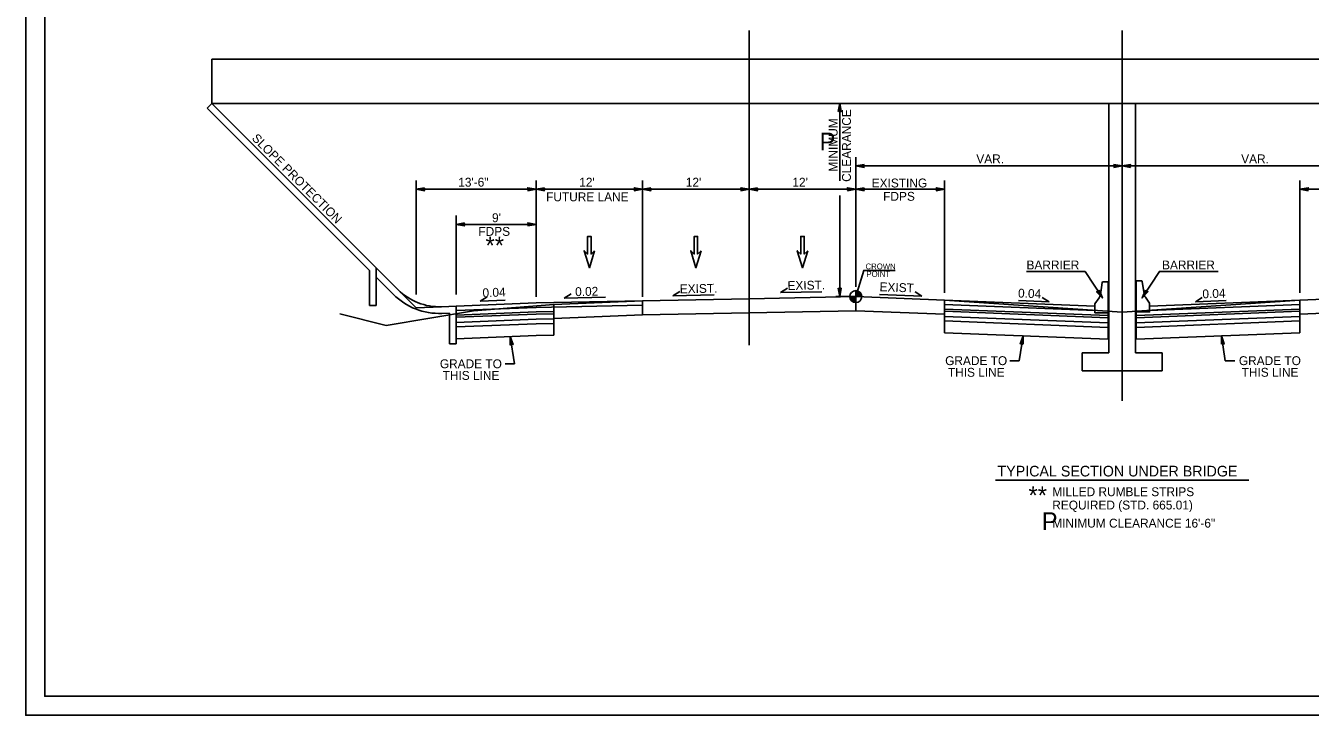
# Model space of a CAD drawing. Extents: x 1553195 to 1553792, y 810516 to 810787.
# Drawn here: x 1553422.4 to 1553567, y 810629 to 810706.7 of the extents above; entities that cross this region are included whole.
import ezdxf

# ---------------------------------------------------------------- set-up
doc = ezdxf.new("R2010")
doc.units = 0
for name, color, linetype in [('Old_Level_11', 7, 'Continuous'), ('Prop Dimension', 7, 'Continuous'), ('Prop DSN Text', 7, 'Continuous'), ('Prop Pavement Schedule Description CELL', 7, 'Continuous'), ('Prop Terminator CELL', 7, 'Continuous'), ('Prop Typical Section', 7, 'Continuous'), ('Sheet Plan CELL', 7, 'Continuous'), ('Typical Arrow Superelevation CELL', 7, 'Continuous'), ('Typical Grade Point Symbol CELL', 7, 'Continuous'), ('Typical Pavement Slope CELL', 7, 'Continuous'), ('Typical Shoulder Slope CELL', 7, 'Continuous'), ('Typical Text ID Circle CELL', 7, 'Continuous'), ('z - Construction', 7, 'Continuous')]:
    doc.layers.add(name, color=color, linetype=linetype)

msp = doc.modelspace()

# ---------------------------------------------------------------- linework, layer by layer
at = {"layer": 'Old_Level_11'}
for p, q in [((1553515.16, 810676.15), (1553515.83, 810676.15)), ((1553515.83, 810676.15), (1553515.83, 810676.82)), ((1553516.5, 810676.15), (1553515.83, 810676.15)), ((1553515.83, 810675.47), (1553515.83, 810676.15)), ((1553515.83, 810676.15), (1553515.83, 810675.47))]:
    msp.add_line(p, q, dxfattribs=at)
for points in [[(1553515.16, 810676.15), (1553515.16, 810676.07)], [(1553515.18, 810676.15), (1553515.18, 810675.99)], [(1553515.19, 810676.15), (1553515.19, 810675.95)], [(1553515.2, 810676.15), (1553515.2, 810675.91)], [(1553515.22, 810676.15), (1553515.22, 810675.87)], [(1553515.23, 810676.15), (1553515.23, 810675.85)], [(1553515.24, 810676.15), (1553515.24, 810675.82)], [(1553515.26, 810676.15), (1553515.26, 810675.8)], [(1553515.27, 810676.15), (1553515.27, 810675.78)], [(1553515.28, 810676.15), (1553515.28, 810675.76)], [(1553515.3, 810676.15), (1553515.3, 810675.74)], [(1553515.31, 810676.15), (1553515.31, 810675.72)], [(1553515.32, 810676.15), (1553515.32, 810675.71)], [(1553515.34, 810676.15), (1553515.34, 810675.69)], [(1553515.35, 810676.15), (1553515.35, 810675.68)], [(1553515.36, 810676.15), (1553515.36, 810675.66)], [(1553515.38, 810676.15), (1553515.38, 810675.65)], [(1553515.39, 810676.15), (1553515.39, 810675.64)], [(1553515.4, 810676.15), (1553515.4, 810675.63)], [(1553515.42, 810676.15), (1553515.42, 810675.62)], [(1553515.43, 810676.15), (1553515.43, 810675.61)], [(1553515.45, 810676.15), (1553515.45, 810675.6)], [(1553515.46, 810676.15), (1553515.46, 810675.59)], [(1553515.47, 810676.15), (1553515.47, 810675.58)], [(1553515.49, 810676.15), (1553515.49, 810675.57)], [(1553515.5, 810676.15), (1553515.5, 810675.56)], [(1553515.51, 810676.15), (1553515.51, 810675.55)], [(1553515.53, 810676.15), (1553515.53, 810675.55)], [(1553515.54, 810676.15), (1553515.54, 810675.54)], [(1553515.55, 810676.15), (1553515.55, 810675.54)], [(1553515.57, 810676.15), (1553515.57, 810675.53)], [(1553515.58, 810676.15), (1553515.58, 810675.52)], [(1553515.59, 810676.15), (1553515.59, 810675.52)], [(1553515.61, 810676.15), (1553515.61, 810675.51)], [(1553515.62, 810676.15), (1553515.62, 810675.51)], [(1553515.63, 810676.15), (1553515.63, 810675.5)], [(1553515.65, 810676.15), (1553515.65, 810675.5)], [(1553515.66, 810676.15), (1553515.66, 810675.5)], [(1553515.67, 810676.15), (1553515.67, 810675.49)], [(1553515.69, 810676.15), (1553515.69, 810675.49)], [(1553515.7, 810676.15), (1553515.7, 810675.49)], [(1553515.71, 810676.15), (1553515.71, 810675.48)], [(1553515.73, 810676.15), (1553515.73, 810675.48)], [(1553515.74, 810676.15), (1553515.74, 810675.48)], [(1553515.75, 810676.15), (1553515.75, 810675.48)], [(1553515.77, 810676.15), (1553515.77, 810675.48)], [(1553515.78, 810676.15), (1553515.78, 810675.48)], [(1553515.79, 810676.15), (1553515.79, 810675.48)], [(1553515.81, 810676.15), (1553515.81, 810675.47)], [(1553515.82, 810676.15), (1553515.82, 810675.47), (1553515.82, 810675.47)], [(1553515.84, 810676.82), (1553515.84, 810676.82), (1553515.84, 810676.15)], [(1553515.85, 810676.82), (1553515.85, 810676.15)], [(1553515.86, 810676.82), (1553515.86, 810676.15)], [(1553515.88, 810676.82), (1553515.88, 810676.15)], [(1553515.89, 810676.81), (1553515.89, 810676.15)], [(1553515.9, 810676.81), (1553515.9, 810676.15)], [(1553515.92, 810676.81), (1553515.92, 810676.15)], [(1553515.93, 810676.81), (1553515.93, 810676.15)], [(1553515.94, 810676.81), (1553515.94, 810676.15)], [(1553515.96, 810676.81), (1553515.96, 810676.15)], [(1553515.97, 810676.8), (1553515.97, 810676.15)], [(1553515.99, 810676.8), (1553515.99, 810676.15)], [(1553516, 810676.8), (1553516, 810676.15)], [(1553516.01, 810676.79), (1553516.01, 810676.15)], [(1553516.03, 810676.79), (1553516.03, 810676.15)], [(1553516.04, 810676.78), (1553516.04, 810676.15)], [(1553516.05, 810676.78), (1553516.05, 810676.15)], [(1553516.07, 810676.78), (1553516.07, 810676.15)], [(1553516.08, 810676.77), (1553516.08, 810676.15)], [(1553516.09, 810676.76), (1553516.09, 810676.15)], [(1553516.11, 810676.76), (1553516.11, 810676.15)], [(1553516.12, 810676.75), (1553516.12, 810676.15)], [(1553516.13, 810676.75), (1553516.13, 810676.15)], [(1553516.15, 810676.74), (1553516.15, 810676.15)], [(1553516.16, 810676.73), (1553516.16, 810676.15)], [(1553516.17, 810676.72), (1553516.17, 810676.15)], [(1553516.19, 810676.72), (1553516.19, 810676.15)], [(1553516.2, 810676.71), (1553516.2, 810676.15)], [(1553516.21, 810676.7), (1553516.21, 810676.15)], [(1553516.23, 810676.69), (1553516.23, 810676.15)], [(1553516.24, 810676.68), (1553516.24, 810676.15)], [(1553516.25, 810676.67), (1553516.25, 810676.15)], [(1553516.27, 810676.66), (1553516.27, 810676.15)], [(1553516.28, 810676.64), (1553516.28, 810676.15)], [(1553516.29, 810676.63), (1553516.29, 810676.15)], [(1553516.31, 810676.62), (1553516.31, 810676.15)], [(1553516.32, 810676.61), (1553516.32, 810676.15)], [(1553516.33, 810676.59), (1553516.33, 810676.15)], [(1553516.35, 810676.57), (1553516.35, 810676.15)], [(1553516.36, 810676.56), (1553516.36, 810676.15)], [(1553516.37, 810676.54), (1553516.37, 810676.15)], [(1553516.39, 810676.52), (1553516.39, 810676.15)], [(1553516.4, 810676.5), (1553516.4, 810676.15)], [(1553516.41, 810676.48), (1553516.41, 810676.15)], [(1553516.43, 810676.45), (1553516.43, 810676.15)], [(1553516.44, 810676.42), (1553516.44, 810676.15)], [(1553516.46, 810676.39), (1553516.46, 810676.15)], [(1553516.47, 810676.36), (1553516.47, 810676.15)], [(1553516.48, 810676.31), (1553516.48, 810676.15)], [(1553516.5, 810676.24), (1553516.5, 810676.15)]]:
    msp.add_lwpolyline(points, dxfattribs=at)
msp.add_circle((1553515.83, 810676.15), 0.671, dxfattribs=at)
for start, end in [(179.9905, 269.9905), (359.9905, 89.9905)]:
    msp.add_arc((1553515.83, 810676.15), 0.671, start, end, dxfattribs=at)
at = {"layer": 'Prop Dimension'}
for p, q in [((1553473.55, 810675.64), (1553474.32, 810676.13)), ((1553483, 810675.98), (1553483.78, 810676.45)), ((1553483, 810675.98), (1553487.66, 810676.07)), ((1553495.23, 810676.25), (1553496.02, 810676.72)), ((1553495.23, 810676.25), (1553499.89, 810676.34)), ((1553507.36, 810676.61), (1553508.15, 810677.08)), ((1553507.36, 810676.61), (1553512.02, 810676.7)), ((1553523.27, 810676.21), (1553518.49, 810676.4)), ((1553523.27, 810676.21), (1553522.5, 810676.7)), ((1553473.55, 810675.64), (1553476.34, 810675.76)), ((1553537.6, 810675.57), (1553534.15, 810675.71)), ((1553537.6, 810675.57), (1553536.82, 810676.06)), ((1553554.07, 810675.57), (1553554.84, 810676.06)), ((1553554.07, 810675.57), (1553557.52, 810675.71))]:
    msp.add_line(p, q, dxfattribs=at)
at = {"layer": 'Prop DSN Text'}
for points in [[(1553513.86, 810696.99), (1553514.02, 810697.93), (1553514.19, 810696.99), (1553514.02, 810697.11)], [(1553516.77, 810691.02), (1553515.83, 810690.86), (1553516.77, 810690.69), (1553516.65, 810690.86)], [(1553544.89, 810690.7), (1553545.83, 810690.86), (1553544.89, 810691.02), (1553545.01, 810690.86)], [(1553546.77, 810690.7), (1553545.83, 810690.86), (1553546.77, 810691.02), (1553546.65, 810690.86)], [(1553467.27, 810688.39), (1553466.33, 810688.23), (1553467.27, 810688.07), (1553467.15, 810688.23)], [(1553478.89, 810688.07), (1553479.83, 810688.23), (1553478.89, 810688.4), (1553479.01, 810688.23)], [(1553480.77, 810688.39), (1553479.83, 810688.23), (1553480.77, 810688.07), (1553480.65, 810688.23)], [(1553490.89, 810688.07), (1553491.83, 810688.23), (1553490.89, 810688.4), (1553491.01, 810688.23)], [(1553492.77, 810688.39), (1553491.83, 810688.23), (1553492.77, 810688.07), (1553492.65, 810688.23)], [(1553502.89, 810688.07), (1553503.83, 810688.23), (1553502.89, 810688.4), (1553503.01, 810688.23)], [(1553504.77, 810688.39), (1553503.83, 810688.23), (1553504.77, 810688.07), (1553504.65, 810688.23)], [(1553514.89, 810688.07), (1553515.83, 810688.23), (1553514.89, 810688.4), (1553515.01, 810688.23)], [(1553516.77, 810688.39), (1553515.83, 810688.23), (1553516.77, 810688.07), (1553516.65, 810688.23)], [(1553524.89, 810688.07), (1553525.83, 810688.23), (1553524.89, 810688.4), (1553525.01, 810688.23)], [(1553566.77, 810688.07), (1553565.83, 810688.23), (1553566.77, 810688.4), (1553566.65, 810688.23)], [(1553471.77, 810684.44), (1553470.83, 810684.28), (1553471.77, 810684.11), (1553471.65, 810684.28)], [(1553478.89, 810684.12), (1553479.83, 810684.28), (1553478.89, 810684.45), (1553479.01, 810684.28)], [(1553513.86, 810677.08), (1553514.02, 810676.15), (1553514.19, 810677.09), (1553514.02, 810676.97)], [(1553543.22, 810676.87), (1553543.6, 810676), (1553542.94, 810676.69), (1553543.15, 810676.68)], [(1553548.44, 810676.87), (1553548.06, 810676), (1553548.72, 810676.69), (1553548.51, 810676.68)], [(1553534.68, 810670.78), (1553534.66, 810671.73), (1553534.35, 810670.82), (1553534.53, 810670.91)], [(1553556.99, 810670.78), (1553557, 810671.73), (1553557.31, 810670.82), (1553557.13, 810670.91)], [(1553476.91, 810670.69), (1553476.93, 810671.64), (1553477.24, 810670.74), (1553477.06, 810670.83)]]:
    msp.add_lwpolyline(points, close=True, dxfattribs=at)
at = {"layer": 'Prop Pavement Schedule Description CELL'}
for p, q in [((1553466.33, 810676.37), (1553466.33, 810689.23)), ((1553470.83, 810676.38), (1553470.83, 810685.28)), ((1553534.23, 810668.92), (1553534.66, 810671.73)), ((1553557.43, 810668.92), (1553557, 810671.73)), ((1553477.4, 810668.56), (1553476.93, 810671.64)), ((1553534.23, 810668.92), (1553533.17, 810668.92)), ((1553557.43, 810668.92), (1553558.49, 810668.92)), ((1553477.4, 810668.56), (1553476.34, 810668.56)), ((1553531.57, 810655.46), (1553560.09, 810655.46))]:
    msp.add_line(p, q, dxfattribs=at)
at = {"layer": 'Prop Terminator CELL'}
msp.add_lwpolyline([(1553663.91, 810631.13), (1553663.91, 810784.39), (1553424.51, 810784.39), (1553424.51, 810631.13)], close=True, dxfattribs=at)
at = {"layer": 'Prop Typical Section'}
for p, q in [((1553503.83, 810670.66), (1553503.83, 810706.13)), ((1553545.83, 810664.39), (1553545.83, 810706.13))]:
    msp.add_line(p, q, dxfattribs=at)
for points in [[(1553486.42, 810681.31), (1553486.02, 810680.93), (1553486.02, 810682.93), (1553485.64, 810682.93), (1553485.64, 810680.93), (1553485.24, 810681.31), (1553485.83, 810679.4)], [(1553498.42, 810681.31), (1553498.02, 810680.93), (1553498.02, 810682.93), (1553497.64, 810682.93), (1553497.64, 810680.93), (1553497.24, 810681.31), (1553497.83, 810679.4)], [(1553498.42, 810681.31), (1553498.02, 810680.93), (1553498.02, 810682.93), (1553497.64, 810682.93), (1553497.64, 810680.93), (1553497.24, 810681.31), (1553497.83, 810679.4)], [(1553510.42, 810681.31), (1553510.02, 810680.93), (1553510.02, 810682.93), (1553509.64, 810682.93), (1553509.64, 810680.93), (1553509.24, 810681.31), (1553509.83, 810679.4)], [(1553510.42, 810681.31), (1553510.02, 810680.93), (1553510.02, 810682.93), (1553509.64, 810682.93), (1553509.64, 810680.93), (1553509.24, 810681.31), (1553509.83, 810679.4)]]:
    msp.add_lwpolyline(points, close=True, dxfattribs=at)
at = {"layer": 'Sheet Plan CELL'}
msp.add_lwpolyline([(1553666.04, 810628.99), (1553666.04, 810786.53), (1553422.37, 810786.53), (1553422.37, 810628.99)], close=True, dxfattribs=at)
at = {"layer": 'Typical Arrow Superelevation CELL'}
for p, q in [((1553443.33, 810702.89), (1553648.33, 810702.89)), ((1553443.33, 810702.89), (1553443.33, 810697.89)), ((1553443.33, 810697.89), (1553442.8, 810697.36)), ((1553464.3, 810676.92), (1553443.33, 810697.89)), ((1553443.33, 810697.89), (1553648.33, 810697.89)), ((1553544.33, 810674.5), (1553544.33, 810697.89)), ((1553547.33, 810674.02), (1553547.33, 810697.89)), ((1553461.08, 810679.08), (1553442.8, 810697.36)), ((1553461.08, 810679.08), (1553461.08, 810675.15)), ((1553461.83, 810679.39), (1553461.83, 810675.15)), ((1553463.77, 810676.39), (1553461.83, 810678.33)), ((1553466.33, 810674.89), (1553464.3, 810676.92)), ((1553461.83, 810675.15), (1553461.08, 810675.15)), ((1553469.2, 810675), (1553466.33, 810674.89)), ((1553470.83, 810675.07), (1553469.2, 810675)), ((1553470.83, 810675.07), (1553470.83, 810670.81)), ((1553470.08, 810674.29), (1553469.23, 810674.25)), ((1553470.08, 810674.29), (1553470.08, 810670.81)), ((1553544.33, 810674.5), (1553544.33, 810669.8)), ((1553547.33, 810674.02), (1553547.33, 810669.8)), ((1553470.83, 810670.81), (1553470.08, 810670.81)), ((1553544.33, 810669.8), (1553541.33, 810669.8)), ((1553541.33, 810669.8), (1553541.33, 810667.8)), ((1553550.33, 810669.8), (1553547.33, 810669.8)), ((1553550.33, 810669.8), (1553550.33, 810667.8)), ((1553550.33, 810667.8), (1553541.33, 810667.8))]:
    msp.add_line(p, q, dxfattribs=at)
for radius in [7.32, 6.57]:
    msp.add_arc((1553468.94, 810681.57), radius, 225, 272.2621, dxfattribs=at)
at = {"layer": 'Typical Grade Point Symbol CELL'}
for p, q in [((1553515.83, 810676.15), (1553503.83, 810675.91)), ((1553515.83, 810676.15), (1553525.83, 810675.75)), ((1553515.83, 810676.15), (1553515.83, 810674.56)), ((1553575.83, 810676.15), (1553565.83, 810675.75)), ((1553481.83, 810675.27), (1553472.78, 810674.54)), ((1553491.83, 810675.67), (1553481.83, 810675.27)), ((1553481.83, 810675.27), (1553481.83, 810673.68)), ((1553503.83, 810675.91), (1553491.83, 810675.67)), ((1553491.83, 810675.67), (1553491.83, 810674.08)), ((1553525.83, 810675.75), (1553525.83, 810674.16)), ((1553525.83, 810675.75), (1553545.83, 810674.39)), ((1553565.83, 810675.75), (1553545.83, 810674.39)), ((1553565.83, 810675.75), (1553565.83, 810674.16)), ((1553457.75, 810674.21), (1553462.96, 810672.9)), ((1553472.78, 810674.54), (1553462.96, 810672.9)), ((1553491.83, 810674.08), (1553481.83, 810673.68)), ((1553503.83, 810674.32), (1553491.83, 810674.08)), ((1553515.83, 810674.56), (1553503.83, 810674.32)), ((1553515.83, 810674.56), (1553525.83, 810674.16)), ((1553575.83, 810674.56), (1553565.83, 810674.16))]:
    msp.add_line(p, q, dxfattribs=at)
at = {"layer": 'Typical Pavement Slope CELL'}
for p, q in [((1553479.83, 810675.43), (1553470.83, 810675.07)), ((1553479.83, 810674.93), (1553470.83, 810674.57)), ((1553479.83, 810675.43), (1553491.83, 810675.67)), ((1553479.83, 810674.93), (1553491.83, 810675.17)), ((1553525.83, 810675.75), (1553542.76, 810675.07)), ((1553525.83, 810675.25), (1553542.76, 810674.57)), ((1553525.83, 810674.75), (1553544.26, 810674.01)), ((1553565.83, 810674.75), (1553547.41, 810674.01)), ((1553565.83, 810675.75), (1553548.91, 810675.07)), ((1553565.83, 810675.25), (1553548.91, 810674.57)), ((1553479.83, 810674.43), (1553470.83, 810674.07)), ((1553479.83, 810674.18), (1553470.83, 810673.82)), ((1553479.83, 810673.59), (1553470.83, 810673.23)), ((1553479.83, 810674.43), (1553481.83, 810674.47)), ((1553479.83, 810674.18), (1553481.83, 810674.22)), ((1553479.83, 810673.59), (1553481.83, 810673.63)), ((1553481.83, 810673.68), (1553481.83, 810671.8)), ((1553525.83, 810674.5), (1553544.26, 810673.76)), ((1553525.83, 810674.16), (1553525.83, 810672.08)), ((1553525.83, 810673.91), (1553544.26, 810673.18)), ((1553525.83, 810673.41), (1553544.26, 810672.68)), ((1553544.26, 810674.32), (1553544.26, 810671.34)), ((1553565.83, 810674.5), (1553547.41, 810673.76)), ((1553547.41, 810674.32), (1553547.41, 810671.34)), ((1553565.83, 810673.91), (1553547.41, 810673.18)), ((1553565.83, 810673.41), (1553547.41, 810672.68)), ((1553565.83, 810674.16), (1553565.83, 810672.08)), ((1553479.83, 810673.09), (1553470.83, 810672.73)), ((1553479.83, 810671.76), (1553470.83, 810671.4)), ((1553479.83, 810673.09), (1553481.83, 810673.13)), ((1553479.83, 810671.76), (1553481.83, 810671.8)), ((1553525.83, 810672.08), (1553544.26, 810671.34)), ((1553565.83, 810672.08), (1553547.41, 810671.34))]:
    msp.add_line(p, q, dxfattribs=at)
at = {"layer": 'Typical Shoulder Slope CELL'}
for points in [[(1553543.37, 810676.35), (1553543.58, 810677.75)], [(1553544.26, 810674.32), (1553544.26, 810677.82), (1553543.66, 810677.82)], [(1553547.41, 810674.42), (1553547.41, 810677.92), (1553548, 810677.92)], [(1553548.29, 810676.45), (1553548.08, 810677.85)], [(1553547.41, 810674.42), (1553548.91, 810674.42), (1553548.91, 810675.17), (1553548.91, 810675.42), (1553548.43, 810676.1)], [(1553544.26, 810674.32), (1553542.76, 810674.32), (1553542.76, 810675.07), (1553542.76, 810675.32), (1553543.23, 810675.99)]]:
    msp.add_lwpolyline(points, dxfattribs=at)
for centre, radius, start, end in [((1553543.66, 810677.74), 0.0833, 90, 171.4692), ((1553548, 810677.84), 0.0833, 8.5308, 90), ((1553542.54, 810676.47), 0.833, 325.008, 351.4692), ((1553549.12, 810676.57), 0.833, 188.5308, 214.992)]:
    msp.add_arc(centre, radius, start, end, dxfattribs=at)
at = {"layer": 'Typical Text ID Circle CELL'}
msp.add_lwpolyline([(1553515.83, 810676.15), (1553516.73, 810679.1), (1553520.27, 810679.1)], dxfattribs=at)
at = {"layer": 'z - Construction'}
for p, q in [((1553514.02, 810689.2), (1553514.02, 810697.93)), ((1553515.83, 810677.26), (1553515.83, 810691.86)), ((1553545.83, 810690.86), (1553515.83, 810690.86)), ((1553545.83, 810690.86), (1553575.83, 810690.86)), ((1553479.83, 810676.11), (1553479.83, 810689.23)), ((1553491.83, 810676.11), (1553491.83, 810689.23)), ((1553525.83, 810676.58), (1553525.83, 810689.23)), ((1553565.83, 810676.58), (1553565.83, 810689.23)), ((1553479.83, 810688.23), (1553466.33, 810688.23)), ((1553491.83, 810688.23), (1553479.83, 810688.23)), ((1553503.83, 810688.23), (1553491.83, 810688.23)), ((1553515.83, 810688.23), (1553503.83, 810688.23)), ((1553525.83, 810688.23), (1553515.83, 810688.23)), ((1553565.83, 810688.23), (1553575.83, 810688.23)), ((1553514.02, 810676.15), (1553514.02, 810687.52)), ((1553479.83, 810684.28), (1553470.83, 810684.28)), ((1553515.83, 810676.15), (1553513.57, 810676.15))]:
    msp.add_line(p, q, dxfattribs=at)
for points in [[(1553535.04, 810678.99), (1553541.65, 810678.99), (1553543.6, 810676)], [(1553556.62, 810678.99), (1553550.01, 810678.99), (1553548.06, 810676)]]:
    msp.add_lwpolyline(points, dxfattribs=at)

# ---------------------------------------------------------------- texts
at = {"layer": 'Prop Pavement Schedule Description CELL'}
for s, rotation, p in [('CLEARANCE', 90, (1553515.28, 810689.07)), ('MINIMUM', 90, (1553513.78, 810690.21)), ('SLOPE PROTECTION', 315, (1553447.76, 810693.9)), ('EXIST.', 1.1459, (1553496.02, 810676.51)), ('EXIST.', 1.1459, (1553508.15, 810676.88)), ('EXIST.', 357.7094, (1553518.49, 810676.76)), ('0.04', 2.2906, (1553473.82, 810676.07)), ('0.02', 1.1459, (1553484.24, 810676.2)), ('0.04', 357.7094, (1553534.08, 810676.05)), ('0.04', 2.2906, (1553554.87, 810675.94))]:
    msp.add_text(s, height=1, rotation=rotation, dxfattribs=at).set_placement(p)
for s, height, p in [('P', 2, (1553511.75, 810692.62)), ('VAR.', 1, (1553529.4, 810691.16)), ('VAR.', 1, (1553559.22, 810691.16)), ('13\'-6"', 1, (1553471.07, 810688.53)), ("12'", 1, (1553484.69, 810688.53)), ("12'", 1, (1553496.69, 810688.53)), ("12'", 1, (1553508.69, 810688.53)), ('EXISTING', 1, (1553517.62, 810688.44)), ('FUTURE LANE', 1, (1553480.96, 810686.88)), ('FDPS', 1, (1553518.91, 810686.94)), ("9'", 1, (1553474.87, 810684.53)), ('FDPS', 1, (1553473.34, 810682.99)), ('**', 2, (1553474.14, 810680.91)), ('BARRIER', 1, (1553535.05, 810679.21)), ('BARRIER', 1, (1553550.31, 810679.21)), ('GRADE TO ', 1, (1553469, 810668.08)), ('GRADE TO ', 1, (1553525.89, 810668.43)), ('GRADE TO ', 1, (1553558.96, 810668.43)), ('THIS LINE', 1, (1553469.31, 810666.77)), ('THIS LINE', 1, (1553526.2, 810667.12)), ('THIS LINE', 1, (1553559.27, 810667.12)), ('TYPICAL SECTION UNDER BRIDGE', 1.2, (1553531.78, 810655.89)), ('**', 2, (1553535.27, 810652.77)), ('MILLED RUMBLE STRIPS', 1, (1553537.95, 810653.67)), ('REQUIRED (STD. 665.01)', 1, (1553537.95, 810652.17)), ('P', 2, (1553536.76, 810649.85)), ('MINIMUM CLEARANCE 16\'-6"', 1, (1553537.95, 810650.13))]:
    msp.add_text(s, height=height, dxfattribs=at).set_placement(p)
at = {"layer": 'Typical Text ID Circle CELL'}
for s, p in [('CROWN', (1553516.93, 810679.22)), ('POINT', (1553517.03, 810678.36))]:
    msp.add_text(s, height=0.652, dxfattribs=at).set_placement(p)

doc.saveas('drawing.dxf')
